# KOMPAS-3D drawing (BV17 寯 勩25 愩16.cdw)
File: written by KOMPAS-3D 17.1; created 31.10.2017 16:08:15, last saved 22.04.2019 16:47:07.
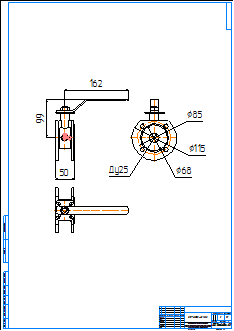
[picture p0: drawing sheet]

Sheet 1: A1, portrait

Title block, sheet 1: name: BV17 МФ Ду25 Ру16; material: Внимание! Данный продукт является объектом авторского права ООО «Торговый Дом АДЛ». / Запрещается изменение, копирование, распространение / (в том числе путем копирования на другие сайты и ресурсы в Интернете) / или любое иное использование информации и объектов без предварительного / согласия правообладателя (ООО «Торговый Дом АДЛ»).; mass: 1; sheets: 1; organisation: ООО "Торговый дом АДЛ"; sheet format: A1; stored path: \\adlc.lan\data\АДЛ_ПКД\3D-модели\ADL production\Краны шаровые серии BV\BV17 МФ Нержавеющие Ру16\KOMPAS 2D\BV17 МФ Ду25 Ру16.cdw

Views: Вид 1, Проекционный вид 2, Проекционный вид 3
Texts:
  kka
  adl
Dimensions and other numbers on the sheet: 50; 162; 99; 25; 115; 85; 68; 1:1; 1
